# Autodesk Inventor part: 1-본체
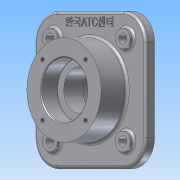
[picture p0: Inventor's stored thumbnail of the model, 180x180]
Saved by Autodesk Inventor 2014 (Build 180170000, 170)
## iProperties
Created: 2015-09
Part Number: 1-본체
Material: 알루미늄 6061
Document SubType Name: Modeling
Designer: study
Density: 2.71 g/cm^3
Appearance: 알루미늄 - 평지
Mass: 1464.68 g
Surface Area: 800.934 cm^2
Volume: 540.471 cm^3
Author: study
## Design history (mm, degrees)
sketch "스케치1"
  geometry: L1 (-75, 75)-(75, 75); L2 (75, 75)-(75, -75); L3 (75, -75)-(-75, -75); L4 (-75, -75)-(-75, 75); L5 (-75, 75)-(75, -75); L6 (75, 75)-(-75, -75); 1 further point
  constraints: 12 end point, 2 midpoint, 2 parallel, 2 perpendicular, 1 horizontal
  dimensions: "d0" = 150 distance of L1.start L1.end
extrude "돌출1" new body sketch "스케치1" distance "d1" = 12; taper "d2" = 0 deg
sketch "스케치2"
  geometry: C1 r 50 at (0, 0); 1 further point
  constraints: 1 centre point, 1 coincident
  dimensions: "d3" = 100 diameter of C1
extrude "돌출2" join sketch "스케치2" distance "d4" = 23; taper "d5" = 0 deg
node "작업 평면1"
sketch "스케치3"
  geometry: C1 r 50 at (0, 0) reference; 1 further point
extrude "돌출3" join sketch "스케치3" stored distance "d7" = 23; taper "d8" = 0 deg
hole "구멍1" diameter "d11" = 45; stored, may be unused: countersink angle "d15" = 90 deg, drill point angle "d17" = 118 deg; dims "d9" = 10, "d10" = 10, "d12" = 6, "d13" = 62, "d14" = 22, "d16" = 8
hole "구멍2" diameter "d20" = 45; stored, may be unused: countersink angle "d24" = 90 deg, drill point angle "d26" = 118 deg; dims "d18" = 10, "d19" = 10, "d21" = 6, "d22" = 62, "d23" = 22, "d25" = 8
sketch "스케치4"
  geometry: C1 r 50 at (0, 0) reference; C2 r 10 at (-49, 49)
  constraints: 1 centre point
  dimensions: "d27" = 20 diameter of C2; "d28" = 49 horizontal distance of C1.centre C2.centre; "d29" = 49 horizontal distance of C1.centre C2.centre
extrude "돌출4" join sketch "스케치4" distance "d30" = 5; taper "d31" = 0 deg
hole "구멍3" diameter "d34" = 11; stored, may be unused: countersink angle "d38" = 90 deg, drill point angle "d40" = 118 deg; dims "d32" = 10, "d33" = 10, "d35" = 6, "d36" = 62, "d37" = 22, "d39" = 8
sketch "스케치5"
  geometry: L1 (-28.991, -28.991)-(28.991, -28.991); L2 (28.991, -28.991)-(28.991, 28.991); L3 (28.991, 28.991)-(-28.991, 28.991); L4 (-28.991, 28.991)-(-28.991, -28.991); L5 (-28.991, -28.991)-(28.991, 28.991); L6 (28.991, -28.991)-(-28.991, 28.991); C1 r 50 at (0, 0) reference; 4 further points
  constraints: 12 end point, 4 coincident, 2 midpoint, 2 parallel, 2 perpendicular, 1 horizontal
  dimensions: "d44" = 82 distance of L2.end L1.start
hole "구멍4" sketch "스케치5" at (-28.991, 28.991), (-28.991, -28.991), (28.991, -28.991), (28.991, 28.991) diameter "d45" = 4.917; stored, may be unused: countersink angle "d49" = 90 deg, drill point angle "d51" = 118 deg; dims "d46" = 10, "d47" = 62, "d48" = 22, "d50" = 13
node "작업 평면2"
fillet "모깎기1" dims "d52" = 30
fillet "모깎기2" dims "d53" = 3, "d54" = 0.3
chamfer "모따기1" distance "d55" = 1; stored, may be unused: second distance "d56" = 2, angle "d57" = 45 deg
feature "엠보싱1" dims "d59" = 1, "d60" = 0
node "솔리드1"
pattern_circular "원형 패턴1" dims angle "d42" = 360 deg
mirror "대칭1"
sketch "스케치6"
  geometry: C1 r 53 at (0, 0) reference; 1 further point
  constraints: 1 other
  dimensions: "d61" = 65 distance of C1.centre point (0, 65)
